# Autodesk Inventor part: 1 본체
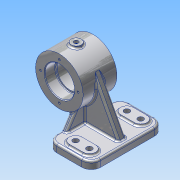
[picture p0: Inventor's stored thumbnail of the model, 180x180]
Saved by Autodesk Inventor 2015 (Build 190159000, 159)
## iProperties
Created: 2023-08
Part Number: 1 본체
Material: 알루미늄 6061
Document SubType Name: Modeling
Designer: 학생용
Density: 2.7 g/cm^3
Appearance: 알루미늄 - 평지
Mass: 777.806 g
Surface Area: 536.474 cm^2
Volume: 288.076 cm^3
Author: 학생용
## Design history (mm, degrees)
sketch "스케치1"
  geometry: L1 (35, 58)-(-35, 58); L2 (-35, 58)-(-35, -58); L3 (-35, -58)-(35, -58); L4 (35, -58)-(35, 58); L5 (35, 58)-(-35, -58); L6 (-35, 58)-(35, -58); 1 further point
  constraints: 12 end point, 2 midpoint, 2 parallel, 1 horizontal, 1 perpendicular
  dimensions: "d0" = 70 distance of L2.end L3.end; "d1" = 116 distance of L1.end L2.end
extrude "돌출1" new body sketch "스케치1" stored distance "d2" = 12; taper "d3" = 0 deg
sketch "스케치2"
  geometry: L1 (-17, -41)-(25, -41); L2 (-7, -31)-(15, -31); L3 (15, -51)-(-7, -51); L4 (35, -58)-(35, 58) reference; A1 r 10 centre (-7, -41) between (-7, -31) and (-7, -51); A2 r 10 centre (15, -41) between (15, -51) and (15, -31); 2 further points
  constraints: 8 end point, 6 point on circle, 4 tangent, 2 centre point, 2 point on line, 1 horizontal, 1 midpoint, 1 parallel
  dimensions: "d4" = 20 distance between parallel lines of L3 L2; "d6" = 41 vertical distance of point (0, 0) point (4, -41); "d7" = 22 distance of A1.centre A2.centre; "d19" = 20 distance from line of L4 A2.centre
extrude "돌출2" join sketch "스케치2" distance "d8" = 3; taper "d9" = 0 deg
sketch "스케치3"
  geometry: C1 r 4.5 at (15, -41); C2 r 4.5 at (-7, -41); A1 r 10 centre (15, -41) between (15, -51) and (15, -31) reference; A2 r 10 centre (-7, -41) between (-7, -31) and (-7, -51) reference; 1 further point
  constraints: 2 centre point, 2 coincident
  dimensions: "d10" = 9 diameter of C2; "d11" = 9 diameter of C1
extrude "돌출3" cut sketch "스케치3" stored distance "d12" = 3; taper "d13" = 0 deg
sketch "스케치4"
  geometry: L1 (-35, -6)-(35, -6) reference; L2 (-11.5, 9)-(-2.5, 9) reference; L3 (-7, 6)-(-7, 9) reference; L4 (-11.5, 9)-(-2.5, 9) reference; L5 (10.5, 9)-(19.5, 9) reference; C1 r 38 at (-47, 64); 1 further point
  constraints: 1 centre point
  dimensions: "d21" = 76 diameter of C1; "d22" = 40 distance from line of L3 C1.centre; "d23" = 70 distance from line of L1 C1.centre
extrude "돌출4" join sketch "스케치4" stored distance "d17" = 54; taper "d18" = 0 deg
sketch "스케치5"
  geometry: L1 (-116, 12)-(0, 12) reference; L2 (-94, 12)-(-68.462, 51.325); L3 (-47.538, 51.325)-(-22, 12); L4 (0, 12)-(0, 0) reference; L5 (-116, 0)-(-116, 12) reference; L6 (-94, 12)-(-22, 12); L7 (-27, 12)-(-7, 12) reference; L8 (-68.462, 51.325)-(-47.538, 51.325); 1 further point
  constraints: 8 end point, 2 point on line, 1 collinear, 1 horizontal
  dimensions: "d24" = 22 distance from line of L4 L3.end; "d25" = 22 distance from line of L5 L2.start; "d26" = 33 deg angle of L5 L2; "d27" = 33 deg angle of L4 L3; "d31" = 39.32489 distance between parallel lines of L1 L8
extrude "돌출5" join sketch "스케치5" distance "d29" = 8; taper "d30" = 0 deg
sketch "스케치6"
  geometry: C1 r 38 at (0, 0) reference; C2 r 23.5 at (0, 0); 1 further point
  constraints: 1 centre point, 1 coincident
  dimensions: "d32" = 47 diameter of C2
extrude "돌출6" cut sketch "스케치6" distance "d33" = 17; taper "d34" = 0 deg
sketch "스케치7"
  geometry: C1 r 38 at (0, 0) reference; C2 r 23.5 at (0, 0); 1 further point
  constraints: 1 centre point, 1 coincident
  dimensions: "d35" = 47 diameter of C2
extrude "돌출7" cut sketch "스케치7" distance "d36" = 17; taper "d37" = 0 deg
sketch "스케치8"
  geometry: C1 r 23.5 at (0, 0) reference; C2 r 20.5 at (0, 0); 1 further point
  constraints: 1 centre point, 1 coincident
  dimensions: "d38" = 41 diameter of C2
extrude "돌출8" cut sketch "스케치8" stored distance "d39" = 17; taper "d40" = 0 deg
sketch "스케치9"
  geometry: L1 (0, 0)-(-116, 0) reference; 2 further points
  constraints: 1 vertical alignment, 1 other
  dimensions: "d41" = 19 distance from line of L1 point (-58, 19)
feature "엠보싱1" sketch "스케치9" dims "d0" = 70, "d1" = 116, "d42" = 0.5, "d43" = 0
sketch "스케치10" dims "d44" = 60
  geometry: C1 r 38 at (0, 0) reference; 3 further points
  constraints: 2 vertical alignment, 1 coincident, 2 other
hole "구멍1" sketch "스케치10" at (0, 30) diameter "d45" = 3.242; stored, may be unused: countersink angle "d49" = 82 deg, drill point angle "d51" = 118 deg; dims "d46" = 8, "d47" = 3.023, "d48" = 2, "d50" = 10
node "작업 평면2"
node "작업 평면5"
  node "작업 평면3"
  node "작업 평면4"
node "작업 평면6"
sketch "스케치11"
  geometry: L1 (-35, -21.749)-(-35, 21.749) reference; L2 (-27, 19.317)-(-27, -19.317) reference; L3 (-85, -27)-(-9, -27) reference; L4 (-9, 27)-(-85, 27) reference; C1 r 8 at (-47, 0); 4 further points; 2 other entities
  constraints: 1 centre point, 1 midpoint, 1 vertical alignment, 2 other
  dimensions: "d56" = 16 diameter of C1
extrude "돌출9" join sketch "스케치11" stored distance "d57" = 0; taper "d58" = 0 deg
sketch "스케치12"
  geometry: C1 r 8 at (0, 0) reference; 2 further points
  constraints: 1 coincident
hole "구멍2" sketch "스케치12" at (0, 0) diameter "d59" = 5.188; stored, may be unused: countersink angle "d63" = 82 deg, drill point angle "d65" = 118 deg; dims "d60" = 40, "d61" = 7, "d62" = 4, "d64" = 41
sketch "스케치13"
  geometry: L1 (-13.471, 81.882)-(27, 6); L2 (35, 6)-(-35, 6) reference; L3 (35, -6)-(35, 6) reference; 2 further points
  constraints: 2 end point, 1 point on line, 3 other
  dimensions: "d66" = 8 distance from line of L3 L1.end
feature "리브1" sketch "스케치13" dims "d67" = 1, "d68" = 12, "d69" = 0, "d70" = 0, "d71" = 1, "d72" = 1
fillet "모깎기1" dims "d73" = 1
chamfer "모따기1" distance "d74" = 1; stored, may be unused: second distance "d75" = 2, angle "d76" = 45 deg
fillet "모깎기2" dims "d77" = 3
fillet "모깎기3" dims "d78" = 15
fillet "모깎기4" dims "d79" = 3
fillet "모깎기5" dims "d80" = 3
fillet "모깎기6" dims "d81" = 3
fillet "모깎기7" dims "d82" = 3
fillet "모깎기8" dims "d83" = 3
node "솔리드1"
mirror "대칭1"
pattern_circular "원형 패턴1" dims angle "d53" = 360 deg
mirror "대칭2"
node "작업 평면1"
node "투영된 루프1"
other parameters: "d55" = -111
